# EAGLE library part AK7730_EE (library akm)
ADC + Audio DSP (EEPROM Boot Mode) 24-Bit, 3 ch ADC /4ch DAC and Input Selector
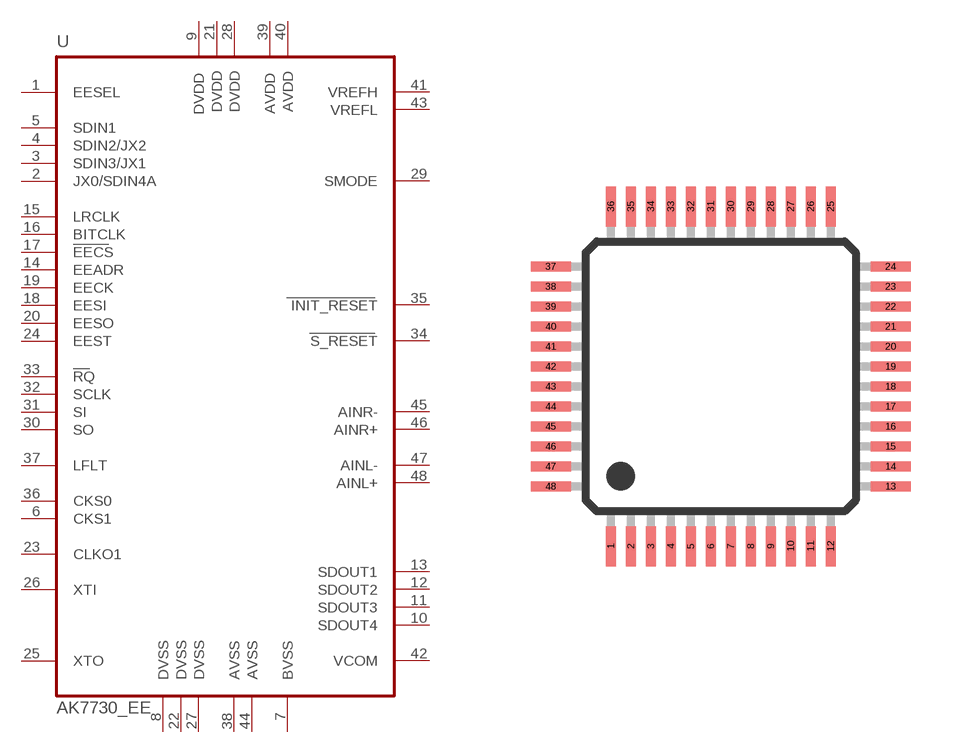
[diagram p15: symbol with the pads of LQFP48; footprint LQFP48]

Designator prefix U

## AK7730_EE  [LQFP48]
1  EESEL  in
2  JX0/SDIN4A  in
3  SDIN3/JX1  in
4  SDIN2/JX2  in
5  SDIN1  in
6  CKS1  in
7  BVSS  pwr
8  DVSS  pwr
9  DVDD  pwr
10  SDOUT4  out
11  SDOUT3  out
12  SDOUT2  out
13  SDOUT1  out
14  EEADR  in
15  LRCLK
16  BITCLK
17  EECS  out
18  EESI  out
19  EECK  out
20  EESO  in
21  DVDD1  pwr
22  DVSS1  pwr
23  CLKO1  out
24  EEST  out
25  XTO  out
26  XTI  in
27  DVSS2  pwr
28  DVDD2  pwr
29  SMODE
30  SO
31  SI  in
32  SCLK  in
33  RQ  in
34  S_RESET  in
35  INIT_RESET  in
36  CKS0  in
37  LFLT
38  AVSS  pwr
39  AVDD  pwr
40  AVDD2  pwr
41  VREFH  in
42  VCOM  out
43  VREFL  in
44  AVSS1  pwr
45  AINR-  in
46  AINR+  in
47  AINL-  in
48  AINL+  in

## Footprint LQFP48 (pad centres in mm)
LQFP48
smd 0.25 x 1: 1 -2.75,-4.25; 2 -2.25,-4.25; 3 -1.75,-4.25; 4 -1.25,-4.25; 5 -0.75,-4.25; 6 -0.25,-4.25; 7 0.25,-4.25; 8 0.75,-4.25; 9 1.25,-4.25; 10 1.75,-4.25; 11 2.25,-4.25; 12 2.75,-4.25; 25 2.75,4.25; 26 2.25,4.25; 27 1.75,4.25; 28 1.25,4.25; 29 0.75,4.25; 30 0.25,4.25; 31 -0.25,4.25; 32 -0.75,4.25; 33 -1.25,4.25; 34 -1.75,4.25; 35 -2.25,4.25; 36 -2.75,4.25
smd 1 x 0.25: 13 4.25,-2.75; 14 4.25,-2.25; 15 4.25,-1.75; 16 4.25,-1.25; 17 4.25,-0.75; 18 4.25,-0.25; 19 4.25,0.25; 20 4.25,0.75; 21 4.25,1.25; 22 4.25,1.75; 23 4.25,2.25; 24 4.25,2.75; 37 -4.25,2.75; 38 -4.25,2.25; 39 -4.25,1.75; 40 -4.25,1.25; 41 -4.25,0.75; 42 -4.25,0.25; 43 -4.25,-0.25; 44 -4.25,-0.75; 45 -4.25,-1.25; 46 -4.25,-1.75; 47 -4.25,-2.25; 48 -4.25,-2.75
